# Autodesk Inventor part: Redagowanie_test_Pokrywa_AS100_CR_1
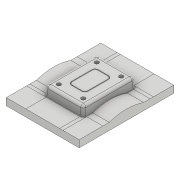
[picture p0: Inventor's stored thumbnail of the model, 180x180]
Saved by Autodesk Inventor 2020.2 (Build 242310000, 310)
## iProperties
Created: 2015-11
Part Number: Redagowanie_test_Pokrywa_AS100_CR_1
Material: Ogólne
Document SubType Name: Modeling
Designer: F.Stasiak
Density: 1 g/cm^3
Appearance: Domyślne
Catalog Web Link: www.expertbooks.pl
Manager: www.cadconsulting.pl
Company: Fabian Stasiak CAD Consulting
Author: F.Stasiak
Subject: Zbiór ćwiczeń. Autodesk Inventor 2020. Kurs Professional
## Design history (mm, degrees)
node "Redagowanie_test_Pokrywa_AS100_CR_Base"
feature "Bryła2::Redagowanie_test_Pokrywa_AS100_CR_Base"
tag "Bryła wyprowadzona2"
node "Bryła2"
feature "Redagowanie_test_Pokrywa_AS100_CR_Base_Bodies"
